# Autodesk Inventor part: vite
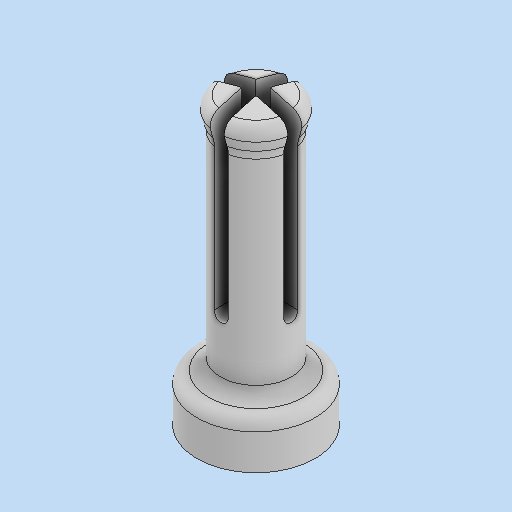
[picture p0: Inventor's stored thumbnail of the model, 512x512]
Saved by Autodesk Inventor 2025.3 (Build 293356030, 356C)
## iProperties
Created: 2026-05
Part Number: vite
Material: Generico
Document SubType Name: Modeling
Designer: R5800u
Density: 1 g/cm^3
Appearance: Default
Author: R5800u
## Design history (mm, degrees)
sketch "Schizzo1"
  geometry: L1 (0, 0)-(1.5, 0); L2 (1.5, 0)-(1.5, 9); L3 (1.5, 9)-(1.7, 9); L4 (1.7, 9)-(1.7, 10); L5 (1.7, 10)-(0, 10.521); L6 (0, 10.521)-(0, 0); L7 (1.5, 0)-(2.5, 0); L8 (2.5, 0)-(2.5, -2); L9 (2.5, -2)-(0, -2); L10 (0, -2)-(0, 0); A1 r 2.6 centre (-0.9, 10) between (1.5, 9) and (1.7, 10)
  constraints: 20 end point, 5 perpendicular, 2 horizontal, 2 point on circle, 1 centre point, 1 parallel, 1 point on line, 1 tangent
  dimensions: "d0" = 1.5 distance of L1.start L1.end; "d1" = 9 distance of L1.end L2.end; "d2" = 0.2 distance of L2.end L3.end; "d3" = 1 distance of L3.end L4.end; "d4" = 1 distance of L1.end L7.end; "d5" = 2 distance of L7.end L8.end
revolve "Rivoluzione1" sketch "Schizzo1" stored, may be unused: angle "d6" = 360 deg
fillet "Raccordo2" dims "d11" = 0.5
node "Piano di lavoro1"
sketch "Schizzo2"
  geometry: L1 (-0.3, 2.707)-(0.3, 2.707); L2 (0.3, 2.707)-(0.3, -2.707); L3 (0.3, -2.707)-(-0.3, -2.707); L4 (-0.3, -2.707)-(-0.3, 2.707); L5 (-0.3, 2.707)-(0.3, -2.707); L6 (0.3, 2.707)-(-0.3, -2.707); L7 (3.09, 0.3)-(-3.09, 0.3); L8 (-3.09, 0.3)-(-3.09, -0.3); L9 (-3.09, -0.3)-(3.09, -0.3); L10 (3.09, -0.3)-(3.09, 0.3); L11 (3.09, 0.3)-(-3.09, -0.3); L12 (-3.09, 0.3)-(3.09, -0.3); 5 further points
  constraints: 24 end point, 4 midpoint, 4 parallel, 2 horizontal, 2 perpendicular
  dimensions: "d13" = 0.6 distance of L2.end L3.end; "d14" = 0.6 distance of L8.end L7.end
extrude "Estrusione1" cut sketch "Schizzo2" distance "d15" = 9; taper "d16" = 0 deg
fillet "Raccordo3" dims "d17" = 0.3
fillet "Raccordo4" dims "d18" = 0.5
fillet "Raccordo5" dims "d19" = 1
sketch "Schizzo4"
  geometry: L1 (-0.3, 0.3)-(0, 0) reference; L2 (0, -1.5)-(-1.299, -0.75); L3 (-1.299, -0.75)-(-1.299, 0.75); L4 (-1.299, 0.75)-(0, 1.5); L5 (0, 1.5)-(1.299, 0.75); L6 (1.299, 0.75)-(1.299, -0.75); L7 (1.299, -0.75)-(0, -1.5); 2 further points
  constraints: 12 end point, 1 coincident, 1 vertical alignment, 14 other
extrude "Estrusione2" cut sketch "Schizzo4" distance "d27" = 2; taper "d28" = 0 deg
fillet "Raccordo6" dims "d29" = 1.2
node "Solido1"
other parameters: "d12" = -13.5
